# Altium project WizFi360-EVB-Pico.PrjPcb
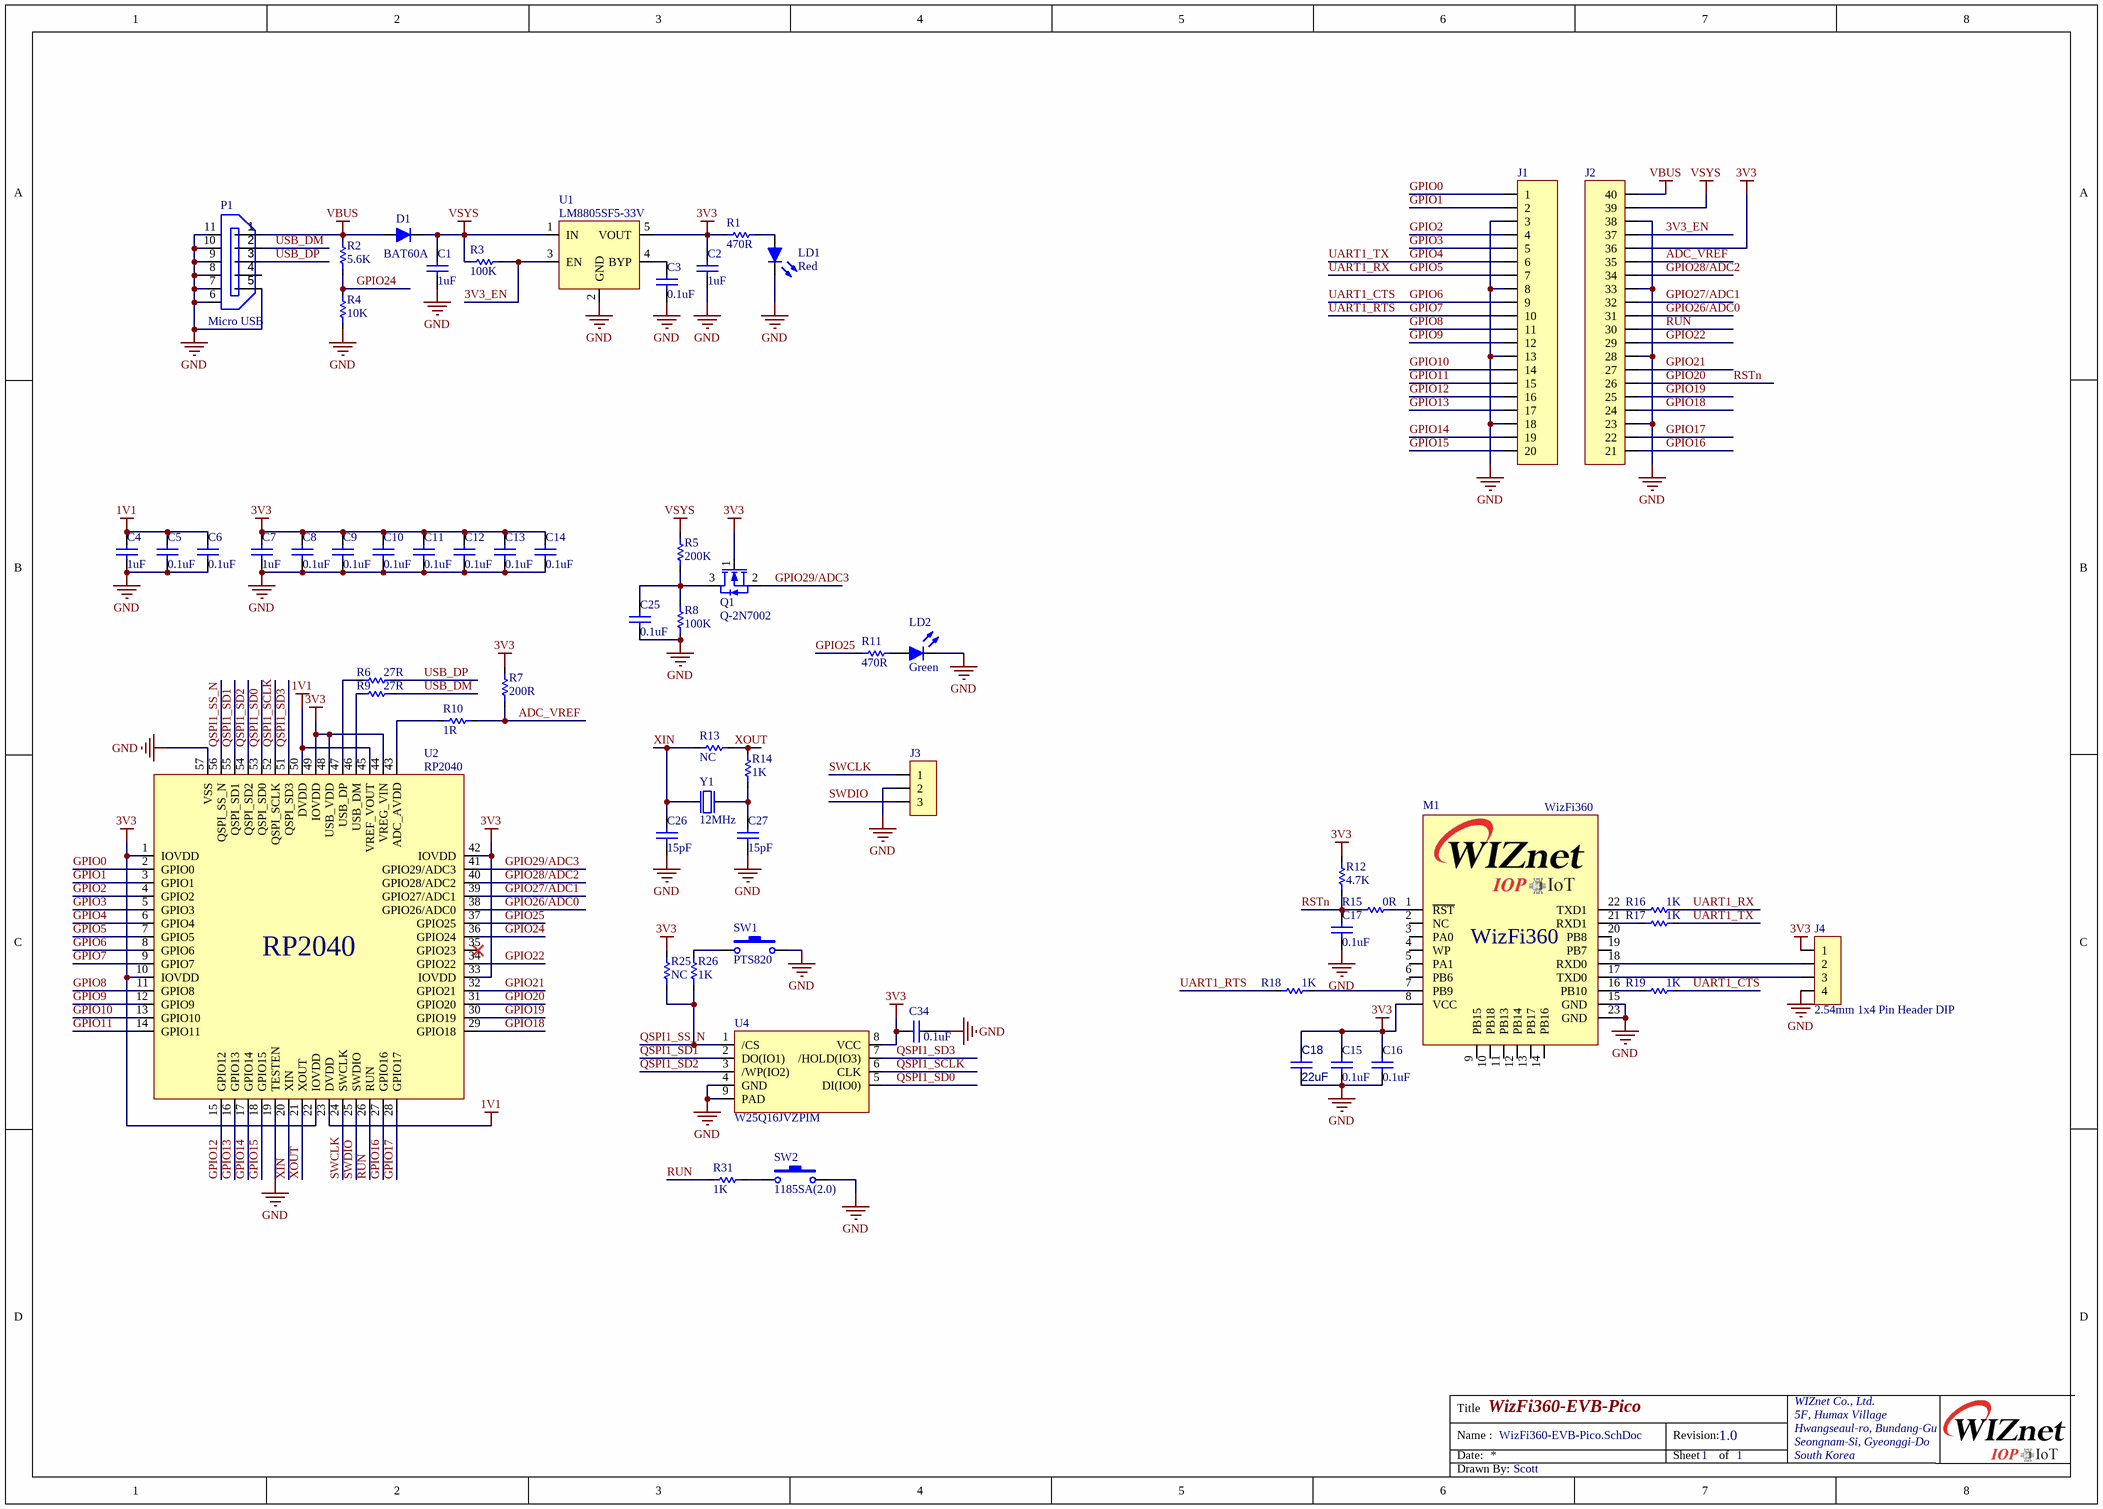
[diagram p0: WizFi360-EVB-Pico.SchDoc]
1 sheet, 60 parts. Net scope: global (net labels, ports and power ports of the same name join across sheets).
Board file: WizFi360-EVB-Pico_V100.PcbDoc

## Sheet WizFi360-EVB-Pico.SchDoc: WizFi360-EVB-Pico
size A3; DrawnBy: Scott; Organization: WIZnet Co., Ltd.; Address1: 5F, Humax Village; Address2: Hwangseaul-ro, Bundang-Gu; Address3: Seongnam-Si, Gyeonggi-Do; Address4: South Korea; Revision: 1.0; SheetNumber: 1; SheetTotal: 1

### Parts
C1  1uF  [CAP-0402]
C2  1uF  [CAP-0402]
C3  0.1uF  [CAP-0402]
C4  1uF  [CAP-0402]
C5  0.1uF  [CAP-0402]
C6  0.1uF  [CAP-0402]
C7  1uF  [CAP-0402]
C8  0.1uF  [CAP-0402]
C9  0.1uF  [CAP-0402]
C10  0.1uF  [CAP-0402]
C11  0.1uF  [CAP-0402]
C12  0.1uF  [CAP-0402]
C13  0.1uF  [CAP-0402]
C14  0.1uF  [CAP-0402]
C15  0.1uF  [CAP-0402]
C16  0.1uF  [CAP-0402]
C17  0.1uF  [CAP-0402]
C18  22uF  [CAP-0805]
C25  0.1uF  [CAP-0402]
C26  15pF  [CAP-0402]
C27  15pF  [CAP-0402]
C34  0.1uF  [CAP-0402]
D1  BAT60A  [SOD-323(1-C,2-A)]
J1  2.54mm 1x20 Pin Header DIP  [IDC-1X20]  (value not drawn)
J2  2.54mm 1x20 Pin Header DIP  [IDC-1X20]  (value not drawn)
J3  2.54mm 1x3 Pin Header DIP  [IDC-1X3]  (value not drawn)
J4  2.54mm 1x4 Pin Header DIP  [IDC-1X4]
LD1  Red  [LED-0603-RED]
LD2  Green  [LED-0603-GREEN]
M1  WizFi360  [WizFi360-PA]
P1  Micro USB  [Micro 5P B DBX 6.4]
Q1  Q-2N7002  [SOT23-3L]
R1  470R  [RES-0402]
R2  5.6K  [RES-0402]
R3  100K  [RES-0402]
R4  10K  [RES-0402]
R5  200K  [RES-0402]
R6  27R  [RES-0402]
R7  200R  [RES-0402]
R8  100K  [RES-0402]
R9  27R  [RES-0402]
R10  1R  [RES-0402]
R11  470R  [RES-0402]
R12  4.7K  [RES-0402]
R13  NC  [RES-0402]
R14  1K  [RES-0402]
R15  0R  [RES-0402]
R16  1K  [RES-0402]
R17  1K  [RES-0402]
R18  1K  [RES-0402]
R19  1K  [RES-0402]
R25  NC  [RES-0402]
R26  1K  [RES-0402]
R31  1K  [RES-0402]
SW1  PTS820  [PTS820]
SW2  1185SA(2.0)  [PTS820]
U1  LM8805SF5-33V  [SOT-23-5L]
U2  RP2040  [RP2040_QFN56(0.4/7X7)]
U4  W25Q16JVZPIM  [WSON8(6X5_1.27)]
Y1  12MHz  [OSC-TZ1067B]

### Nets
1V1: C4.2 C5.2 C6.2 U2.23(DVDD) U2.45(VREF_VOUT) U2.50(DVDD)
3V3: C2.2 C7.2 C8.2 C9.2 C10.2 C11.2 C12.2 C13.2 C14.2 C15.2 C16.2 C18.2 C34.2 J2.16(36) J4.1 M1.8(VCC) Q1.1(G) R1.1 R7.1 R12.2 R25.2 U1.5(VOUT) U2.1(IOVDD) U2.10(IOVDD) U2.22(IOVDD) U2.33(IOVDD) U2.42(IOVDD) U2.44(VREG_VIN) U2.48(USB_VDD) U2.49(IOVDD) U4.8(VCC)
GND: C1.1 C2.1 C3.1 C4.1 C5.1 C6.1 C7.1 C8.1 C9.1 C10.1 C11.1 C12.1 C13.1 C14.1 C15.1 C16.1 C17.1 C18.1 C25.2 C26.2 C27.2 C34.1 J1.3 J1.8 J1.13 J1.18 J2.3(23) J2.8(28) J2.13(33) J2.18(38) J3.2 J4.4 LD1.2(K) LD2.2(K) M1.15(GND) M1.23(GND) P1.5 P1.6 P1.7 P1.8 P1.9 P1.10 P1.11 R4.1 R8.1 SW1.2 SW2.2 U1.2(GND) U2.19(TESTEN) U2.57(VSS) U4.4(GND) U4.9(PAD) Y1.2 Y1.4
VBUS: D1.2(A) J2.20(40) P1.1 R2.2
VSYS: C1.2 D1.1(K) J2.19(39) R3.1 R5.2 U1.1(IN)
3V3_EN: J2.17(37) R3.2 U1.3(EN)
ADC_VREF: J2.15(35) R7.2 R10.2
GPIO0: J1.1 U2.2(GPIO0)
GPIO1: J1.2 U2.3(GPIO1)
GPIO2: J1.4 U2.4(GPIO2)
GPIO3: J1.5 U2.5(GPIO3)
GPIO4: J1.6 R17.2 U2.6(GPIO4)  [also labelled UART1_TX]
GPIO5: J1.7 R16.2 U2.7(GPIO5)  [also labelled UART1_RX]
GPIO6: J1.9 R19.2 U2.8(GPIO6)  [also labelled UART1_CTS]
GPIO7: J1.10 R18.1 U2.9(GPIO7)  [also labelled UART1_RTS]
GPIO8: J1.11 U2.11(GPIO8)
GPIO9: J1.12 U2.12(GPIO9)
GPIO10: J1.14 U2.13(GPIO10)
GPIO11: J1.15 U2.14(GPIO11)
GPIO12: J1.16 U2.15(GPIO12)
GPIO13: J1.17 U2.16(GPIO13)
GPIO14: J1.19 U2.17(GPIO14)
GPIO15: J1.20 U2.18(GPIO15)
GPIO16: J2.1(21) U2.27(GPIO16)
GPIO17: J2.2(22) U2.28(GPIO17)
GPIO18: J2.4(24) U2.29(GPIO18)
GPIO19: J2.5(25) U2.30(GPIO19)
GPIO20: C17.2 J2.6(26) R12.1 R15.1 U2.31(GPIO20)  [also labelled RSTn]
GPIO21: J2.7(27) U2.32(GPIO21)
GPIO22: J2.9(29) U2.34(GPIO22)
GPIO24: R2.1 R4.2 U2.36(GPIO24)
GPIO25: R11.2 U2.37(GPIO25)
GPIO26/ADC0: J2.11(31) U2.38(GPIO26/ADC0)
GPIO27/ADC1: J2.12(32) U2.39(GPIO27/ADC1)
GPIO28/ADC2: J2.14(34) U2.40(GPIO28/ADC2)
GPIO29/ADC3: Q1.2(S) U2.41(GPIO29/ADC3)
QSPI1_SCLK: U2.52(QSPI_SCLK) U4.6(CLK)
QSPI1_SD0: U2.53(QSPI_SD0) U4.5(DI(IO0))
QSPI1_SD1: U2.55(QSPI_SD1) U4.2(DO(IO1))
QSPI1_SD2: U2.54(QSPI_SD2) U4.3(/WP(IO2))
QSPI1_SD3: U2.51(QSPI_SD3) U4.7(/HOLD(IO3))
QSPI1_SS_N: R25.1 R26.1 U2.56(QSPI_SS_N) U4.1(/CS)
RUN: J2.10(30) R31.2 U2.26(RUN)
SWCLK: J3.1 U2.24(SWCLK)
SWDIO: J3.3 U2.25(SWDIO)
USB_DM: P1.2 R9.1
USB_DP: P1.3 R6.1
XIN: C26.1 R13.2 U2.20(XIN) Y1.1(inp)
XOUT: R13.1 R14.2 U2.21(XOUT)
NetC3_2: C3.2 U1.4(BYP)
NetC25_1: C25.1 Q1.3(D) R5.1 R8.2
NetC27_1: C27.1 R14.1 Y1.3(out)
NetJ4_2: J4.2 M1.18(RXD0)
NetJ4_3: J4.3 M1.17(TXD0)
NetLD1_1: LD1.1(A) R1.2
NetLD2_1: LD2.1(A) R11.1
NetM1_1: M1.1(~{RST}) R15.2
NetM1_7: M1.7(PB9) R18.2
NetM1_16: M1.16(PB10) R19.1
NetM1_21: M1.21(RXD1) R17.1
NetM1_22: M1.22(TXD1) R16.1
NetR6_2: R6.2 U2.47(USB_DP)
NetR9_2: R9.2 U2.46(USB_DM)
NetR10_1: R10.1 U2.43(ADC_AVDD)
NetR26_2: R26.2 SW1.1
NetR31_1: R31.1 SW2.1

Not connected (* = marked no-connect by the designer): M1 2(NC) 3(PA0) 4(WP) 5(PA1) 6(PB6) 9(PB15) 10(PB18) 11(PB13) 12(PB14) 13(PB17) 14(PB16) 19(PB7) 20(PB8); P1 4; U2 35(GPIO23)*

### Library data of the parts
C1-C17 C25-C27 C34 = CAP-0402: Ceramic CAP 0402(1005)
C18 = CAP-0805: Ceramic CAP 0805(2012)
D1 = DIODE-BAT60A: Silicon Schottky Diode
LD1 LD2 = LED-0603
P1 = Micro USB 5P DBX6.4: Micro USB B Connector SMD
Q1 = Q-2N7002: N-Channel 60-V (D-S) MOSFET
R1-R19 R25 R26 R31 = RES-0402
SW1 SW2 = ITS-1107(SMD): TACT Switch (SMD)
U1 = LM8805SF5-33V: 600mA CMOS LDO Regulator
U2 = RP2040: Raspverry Pi, Dual ARM Cortex-M0+ @ 133MHz
U4 = W25Q16JVZPIM: 3V 16M-BIT / SERIAL FLASH MEMORY WITH / DUAL/QUAD SPI, QPI & DTR
Y1 = OSC-TZ1067B-12MHz: X-tal 12MHz,3.2x2.5 SMD, CL=20pF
